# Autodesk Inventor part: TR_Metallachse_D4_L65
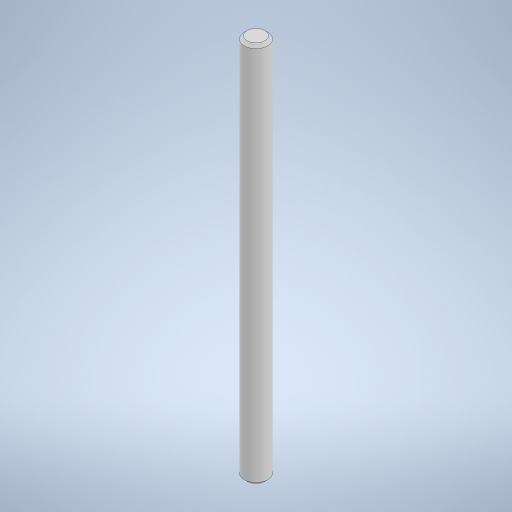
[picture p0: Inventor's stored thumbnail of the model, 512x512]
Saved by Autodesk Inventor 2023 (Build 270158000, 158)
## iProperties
Created: 2023-11
Part Number: TR_Metallachse_D4_L65
Material: Generisch
Document SubType Name: Modeling
Designer: Greiner
Density: 1 g/cm^3
Appearance: Vorgabe
Author: Greiner
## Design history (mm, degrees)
sketch "Skizze1"
  geometry: C1 r 2 at (0, 0); 1 further point
  constraints: 1 centre point, 1 coincident
  dimensions: "d0" = 4 diameter of C1 (= AchsDurchmesser)
extrude "Extrusion1" new body sketch "Skizze1" distance "d1" = 65; taper "d2" = 0 deg
chamfer "Fase1" distance "d3" = 0.5 (= AchsFase); stored, may be unused: second distance "d4" = 2, angle "d5" = 45 deg
node "Volumenkörper1"
other parameters: "Radius" = 2.075 [user parameter], "Fasen" = 0.5 [user parameter], "Dicke" = 0.8 [user parameter], "Breitloch" = 2 [user parameter], "Langloch" = 32 [user parameter], "AchteckUmkreis" = 6 [user parameter], "DAchsAufnahme" = 4.1 [user parameter], "AchsDurchmesser" = 4 [user parameter; used in 1 equation term], "AchsFase" = 0.5 [user parameter; used in 1 equation term]
